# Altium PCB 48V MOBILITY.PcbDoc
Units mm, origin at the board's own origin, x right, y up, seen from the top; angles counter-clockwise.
Board outline 151.6 x 51.1 mm, 2 copper layers (Top Layer, Bottom Layer), stack 1.671 mm thick; 69 components, 31 nets, 153 pads, 0 vias.
Unrouted connection lines stored in the file: 122.
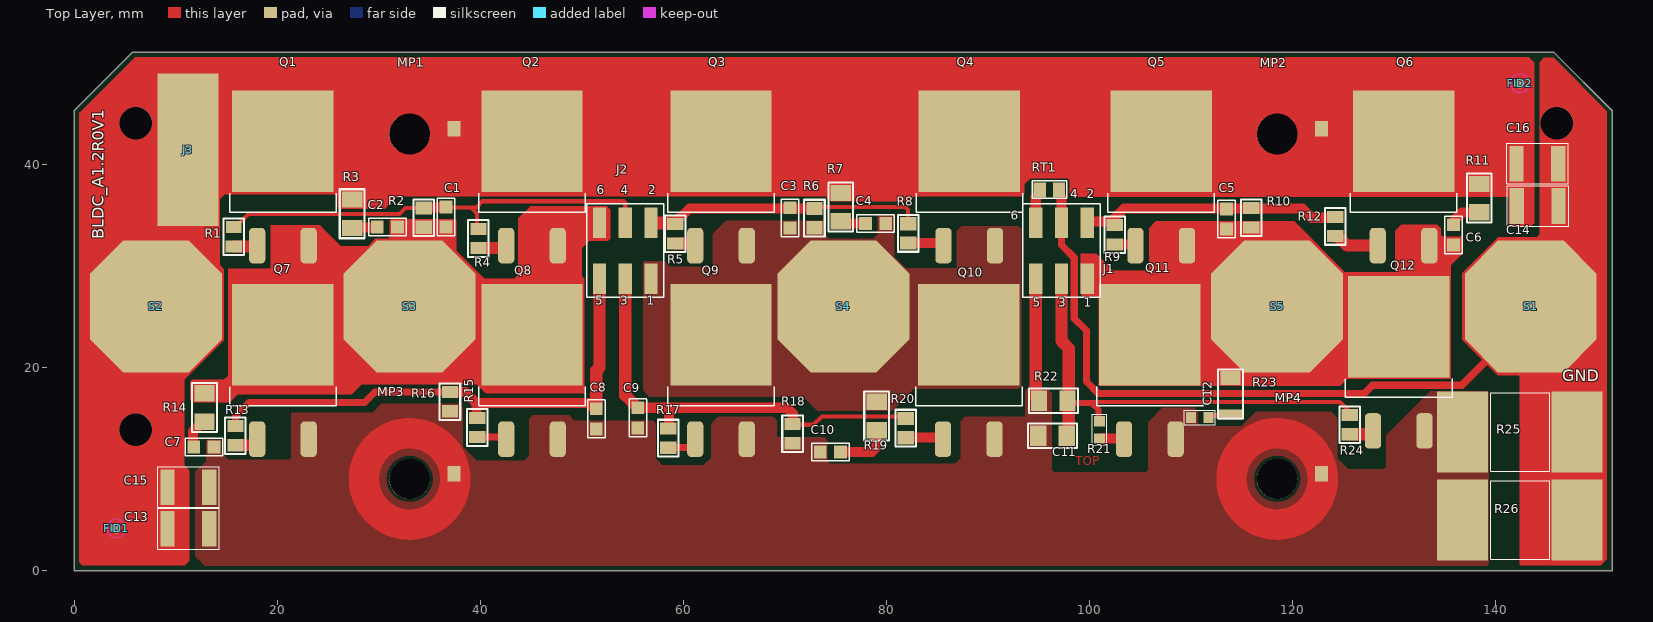
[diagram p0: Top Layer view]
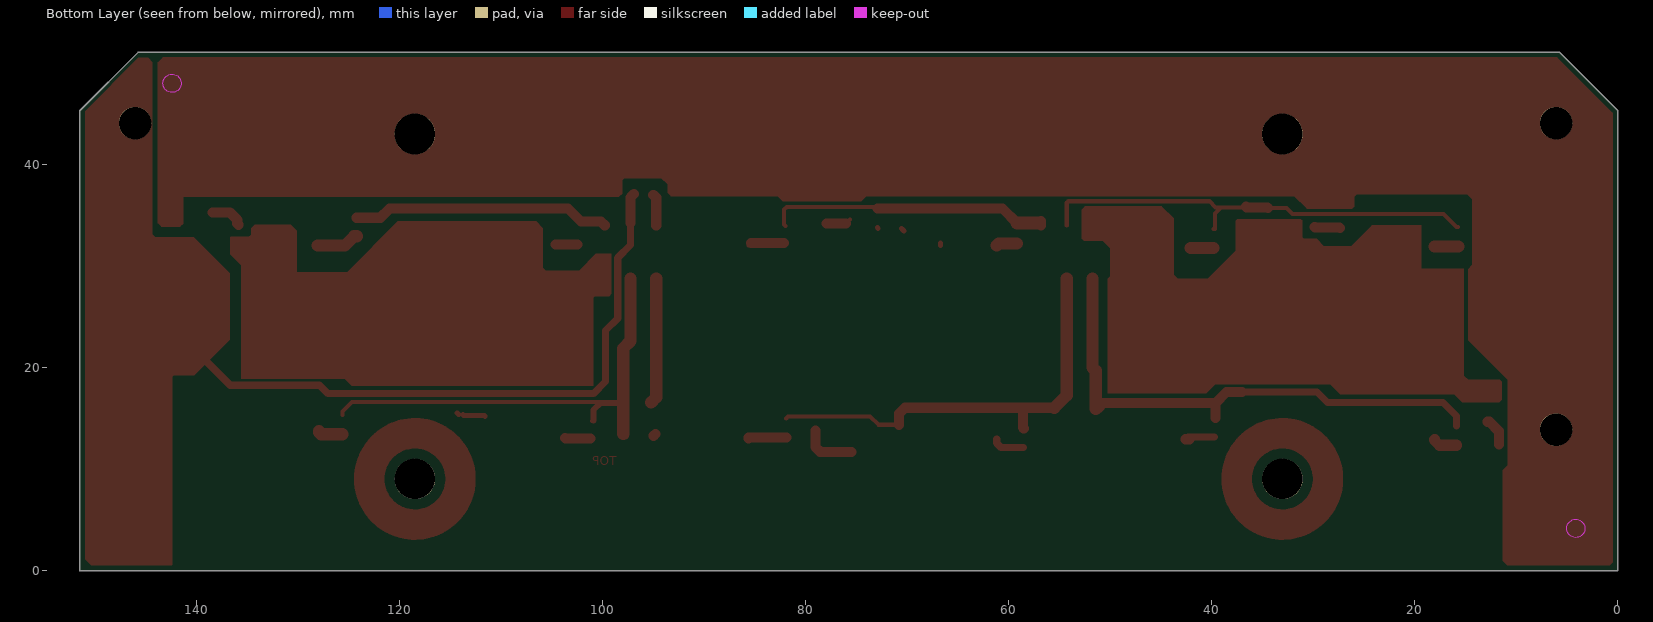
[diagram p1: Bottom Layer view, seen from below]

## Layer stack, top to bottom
Top Solder: solder mask 0.0102, Solder Resist, Dk 3.5
Top Layer: signal copper 0.0356
Dielectric 1: dielectric 1.6, FR-4, Dk 4.8
Bottom Layer: signal copper 0.0356
Bottom Solder: solder mask 0.0102, Solder Resist, Dk 3.5

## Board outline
-0.05,0 -0.05,45.3 cw(c0,45.3) -0.035,45.336 -0.036,45.336 5.664,51.036 5.664,51.035 cw(c5.7,51) 5.7,51.05 145.75,51.05 cw(c145.75,51) 145.786,51.035 145.786,51.036 151.536,45.286 151.535,45.286 cw(c151.5,45.25) 151.55,45.25 151.55,0 cw(c151.5,0) 151.5,-0.05 0,-0.05 cw(c0,0)

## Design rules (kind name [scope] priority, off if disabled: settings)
Clearance Clearance_3 [InNamedPolygon('TOP_LAYER_S2_P030')] p1: gap=0.254 ignorepadtopadclearanceinfootprint=FALSE
Clearance Clearance_2 [InNamedPolygon('TOP_LAYER_S4_P036')] p2: gap=0.254 ignorepadtopadclearanceinfootprint=FALSE
Clearance "GND POLYGON" [InNamedPolygon('TOP_LAYER_GNDINT_P037')] p3: gap=0.254 ignorepadtopadclearanceinfootprint=FALSE
Clearance Clearance_1 [InNamedPolygon('TOP_LAYER_S2_P030')] p4: gap=0.254 ignorepadtopadclearanceinfootprint=FALSE
Clearance [All] p5: gap=0.254 ignorepadtopadclearanceinfootprint=FALSE
PlaneConnect [All] p1: planeconnectstyle=Direct reliefexpansion=0.508 reliefentries=4 reliefconductorwidth=0.254 reliefairgap=0.254
PolygonConnect [All] p1: connectstyle=Direct reliefconductorwidth=0.254 reliefentries=4 polygonreliefangle="90 Angle" airgapwidth=0.254
RoutingVias [All] p1: holewidth=0.711 width=1.27 viastyle="Through Hole" minholewidth=0.711 minwidth=1.27 maxholewidth=0.711 maxwidth=1.27
SolderMaskExpansion [All] p1: expansion=0.102
Width [All] p1: maxlimit=100 minlimit=0.254 preferedwidth=0.4 minimp=50.000000 maximp=50.000000 favimp=50.000000
29 further rules are at their usual default settings.

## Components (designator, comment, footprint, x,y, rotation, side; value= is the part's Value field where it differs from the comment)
C1 "1nF/100V" CAP_0805 36.575,34.822 r90 top
C2 "10nF/100V" CAP_0805 30.81,33.833 r0 top
C3 "1nF/100V" CAP_0805 70.498,34.725 r90 top
C4 "10nF/100V" CAP_0805 78.925,34.194 r180 top
C5 "1nF/100V" CAP_0805 113.525,34.625 r90 top
C6 "10nF/100V" CAP_0805 135.875,33.05 r90 top
C7 "10nF/100V" CAP_0805 12.725,12.145 r180 top
C8 "1nF/100V" CAP_0805 51.398,14.92 r90 top
C9 "1nF/100V" CAP_0805 55.485,15.022 r90 top
C10 "10nF/100V" CAP_0805 74.473,11.67 r0 top
C11 "1nF/100V" MY_1206#1 96.342,13.284 r0 top
C12 "10nF/100V" MY_0603 110.871,15.06 r0 top
C13 "10uF/100V" CAP_1812 11.2,4.094 r180 top
C14 "10uF/100V" CAP_1812 144.182,35.9 r180 top
C15 "10uF/100V" CAP_1812 11.2,8.2 r180 top
C16 "10uF/100V" CAP_1812 144.157,40.075 r180 top
FID1 "FID_1MM" FID_40X20D 4.071,4.127 r0 top
FID2 "FID_1MM" FID_40X20D 142.429,47.992 r90 top
J1 "1241050-3" 1241050-3 97.25,31.5 r180 top locked
J2 "1241050-3" 1241050-3 54.25,31.5 r180 top locked
J3 "78X157 PAD" "VDDS PAD" 10.772,-12.218 r90 top
MP1 "M5x4mm" "POWER PAD" 33,43 r0 top locked
MP2 "M5x4mm" "POWER PAD" 118.5,43 r0 top locked
MP3 "M5x4mm" "POWER PAD" 33,9 r0 top locked
MP4 "M5x4mm" "POWER PAD" 118.5,9 r0 top locked
Q1 "HYG085N04LA1D" D2PAK -12.886,157.146 r0 top
Q2 "HYG085N04LA1D" D2PAK 11.659,157.146 r0 top
Q3 "HYG085N04LA1D" D2PAK 30.289,157.146 r0 top
Q4 "HYG085N04LA1D" D2PAK 54.759,157.146 r0 top
Q5 "HYG085N04LA1D" D2PAK 73.674,157.146 r0 top
Q6 "HYG085N04LA1D" D2PAK 97.559,157.146 r0 top
Q7 "HYG085N04LA1D" D2PAK -12.886,138.071 r0 top
Q8 "HYG085N04LA1D" D2PAK 11.659,138.071 r0 top
Q9 "HYG085N04LA1D" D2PAK 30.289,138.071 r0 top
Q10 "HYG085N04LA1D" D2PAK 54.709,138.071 r0 top
Q11 "HYG085N04LA1D" D2PAK 72.559,138.071 r0 top
Q12 "HYG085N04LA1D" D2PAK 97.088,138.884 r0 top
R1 "39R" MY_0805#1 15.672,32.868 r90 top
R2 "10K" MY_0805#2 34.4,34.75 r90 top
R3 "10R" MY_1206#1 27.305,35.113 r90 top
R4 "39R" MY_0805#3 39.775,32.697 r90 top
R5 "39R" MY_0805#3 59.182,33.168 r90 top
R6 "10K" MY_0805#2 72.9,34.714 r90 top
R7 "10K" MY_1206#1 75.463,35.763 r90 top
R8 "39R" MY_0805#2 82.15,33.194 r90 top
R9 "39R" MY_0805#3 102.489,33.071 r90 top
R10 "10K" MY_0805#3 115.951,34.747 r90 top
R11 "10K" MY_1206#1 138.4,36.65 r90 top
R12 "39R" MY_0805#3 124.231,33.884 r90 top
R13 "39R" MY_0805#3 15.824,13.269 r90 top
R14 "10K" MY_1206#1 12.764,16.019 r90 top
R15 "39R" MY_0805#3 39.675,14.072 r90 top
R16 "10K" MY_0805#3 36.975,16.625 r90 top
R17 "39R" MY_0805#3 58.496,13.03 r90 top
R18 "10K" MY_0805#3 70.739,13.462 r90 top
R19 "100R" MY_1206#1 79,15.175 r90 top
R20 "39R" MY_0805#2 81.9,14.019 r90 top
R21 "39R" MY_0603 101,13.844 r90 top
R22 "10K" MY_1206#1 96.418,16.739 r0 top
R23 "100R" MY_1206#2 113.875,17.35 r90 top
R24 "39R" MY_0805#3 125.654,14.351 r90 top
R25 "0.5mΩ ±1% 5931" "CURRENT SENSE RESISTORS_5931" 142.418,4.953 r180 top
R26 "0.5mΩ ±1% 5931" "CURRENT SENSE RESISTORS_5931" 142.418,13.614 r180 top
RT1 "10K" RES_0805 96.063,37.49 r0 top
S1 "M4x20mm" "15MM SPACER"#1 72.034,23.714 r0 top
S2 "M4x20mm" "15MM SPACER"#2 -65.771,23.258 r0 top
S3 "M4x20mm" "15MM SPACER"#3 -40.446,23.714 r0 top
S4 "M4x20mm" "15MM SPACER"#4 3.354,23.714 r0 top
S5 "M4x20mm" "15MM SPACER"#5 47.104,23.714 r0 top

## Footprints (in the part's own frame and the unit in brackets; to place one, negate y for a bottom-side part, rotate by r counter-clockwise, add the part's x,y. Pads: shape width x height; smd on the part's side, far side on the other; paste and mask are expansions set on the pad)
"15MM SPACER"#1 [mm]
  oct 13x13 smd: 1(71.466,2.286)
  body extent 68.77,-1.71 76.77,6.28, height 15.2
"15MM SPACER"#2 [mm]
  oct 13x13 smd: 1(73.771,2.742)
  body extent 68.77,-1.71 76.77,6.28, height 15.2
"15MM SPACER"#3 [mm]
  oct 13x13 smd: 1(73.446,2.286)
  body extent 68.77,-1.71 76.77,6.28, height 15.2
"15MM SPACER"#4 [mm]
  oct 13x13 smd: 1(72.396,2.286)
  body extent 68.77,-1.71 76.77,6.28, height 15.2
"15MM SPACER"#5 [mm]
  oct 13x13 smd: 1(71.396,2.286)
  body extent 68.77,-1.71 76.77,6.28, height 15.2
1241050-3 [mm] "1241050-3"
  rect 1.3x3 smd: 1(-2.54,-2.754) 2(-2.54,2.754) 3(0,-2.754) 4(0,2.754) 5(2.54,-2.754) 6(2.54,2.754)
  silkscreen extent -3.81,-4.6 3.81,4.6, body extent -3.81,-3.75 3.81,3.75, height 9.57
CAP_0805 [mm] "Ceramic Capacitor"
  rect 1.27x1.27 smd mask+0.076: 1(-1,0) 2(1,0)
  silkscreen extent -1.86,-0.86 1.86,0.86, body extent -1,-0.62 1,0.63, height 0.78
CAP_1812 [mm] "CAP_1812"
  rect 1.4x3.51 smd: 1(-2.057,0) 2(2.057,0)
  silkscreen extent -3.05,-2 3.01,2, body extent -2.25,-1.6 2.25,1.6, height 1.1
"CURRENT SENSE RESISTORS_5931" [mm]
  rect 5x8 smd: 1(-5.65,0) 2(5.65,0)
  silkscreen extent -2.95,-3.89 2.84,3.86, body extent -7.5,-3.87 7.5,3.88, height 1.13
D2PAK [mm]
  rrect50% 1.6x3.5 smd: 1(30.861,-125.152) 2(35.941,-125.152)
  rect 10x10 smd paste-7: 3(33.401,-114.877)
  silkscreen extent 28.15,-121.85 38.65,-120, body extent 28.4,-124.97 38.4,-110.02, height 4.51
FID_40X20D [mm]
  round 1 smd mask+0: ""(0,0)
  Keep-Out Layer circle w0.05: c0,0 r0.9
MY_0603 [mm]
  rect 1x1.1 smd: 1(-0.85,0) 2(0.85,0)
  silkscreen extent -1.52,-0.71 1.52,0.71, body extent -0.8,-0.4 0.8,0.4, height 0.44
MY_0805#1 [mm] "Resister"
  rect 1.2x1.6 smd: 1(-0.95,0)
  rect 1.2x1.5 smd: 2(0.95,0)
  silkscreen extent -1.8,-1.02 1.8,1.02, body extent -1,-0.62 1,0.63, height 0.59
MY_0805#2 [mm]
  rect 1.3x1.6 smd: 1(-0.95,0) 2(0.95,0)
  silkscreen extent -1.8,-1.02 1.8,1.02, body extent -1,-0.62 1,0.63, height 0.59
MY_0805#3 [mm]
  rect 1.2x1.6 smd: 1(-0.95,0) 2(0.95,0)
  silkscreen extent -1.8,-1.02 1.8,1.02, body extent -1,-0.62 1,0.63, height 0.59
MY_1206#1 [mm]
  rect 1.6x2 smd: 1(-1.375,-0.025) 2(1.425,-0.025)
  silkscreen extent -2.39,-1.24 2.44,1.19, body extent -1.57,-0.83 1.63,0.77, height 0.59
MY_1206#2 [mm]
  rect 1x2.5 smd: 1(-2,-0.025)
  rect 1.4x2 smd: 2(1.6,-0.025)
  silkscreen extent -2.39,-1.24 2.44,1.19, body extent -1.57,-0.83 1.63,0.77, height 0.59
"POWER PAD" [mm]
  rect 1.3x1.5 smd mask+0.076: 1(4.379,0.508)
  round 4 hole 4 unplated: ""(0,0)
  Top Layer circle w3: c0,0 r4.5
RES_0805 [mm] "Resister"
  rect 1.2x1.5 smd mask+0.076: 1(0.95,0) 2(-0.95,0)
  silkscreen extent -1.7,-0.84 1.7,0.89, body extent -1,-0.63 1,0.62, height 0.5
"VDDS PAD" [mm]
  rect 15x6 smd: 1(53.661,-0.378)

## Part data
C1 C2 C3 C4 C5 C6 C7 C8 C9 C10 C11 C12: library part CAP_33pF-50V-5%-0805, "33pF ±5% 50V Ceramic Capacitor C0G, NP0 0805 (2012 Metric)", Alternate Part Number-1=NA, Case/Package=0805, Manufacturer=Samsung, Manufacturer Part Number=CL21C330JBANNNC, Supplier Part Number-1=0805N330J500CT
C13 C14 C15 C16: library part CAP_2.2uF-25V-10%-0805, "2.2µF ±10% 25V Ceramic Capacitor X7R 0805 (2012 Metric)", Alternate Part Number-1=NA, Case/Package=0805, Manufacturer=KEMET, Manufacturer Part Number=CL21B225KAFNFNE, Supplier Part Number-1=CL21A225KAFNNNE
FID1 FID2: "Fiducial 40 mil Diameter and 120 mil Mask"
J1 J2: "Connector", Manufacturer_Name="TE Connectivity", Mouser Part Number=571-1241050-3
J3: library part SMD_PAD-78X157, "SMD Pad of 2mm x 4mm 1 pin", Alternate Part Number-1=NA, Case/Package=SMD
MP1 MP2 MP3 MP4: library part 7466105R, "WP-SMBU SMT Internal blind-hole thread with pins, OD 9mm, M5x4mm, 70A", Manufacturer="Wurth Elektronik", Operating Temperature="-55 to +150degC", Rated Current=70A
Q1 Q2 Q3 Q4 Q5 Q6 Q7 Q8 Q9 Q10 Q11 Q12: library part IRFRC20, "HEXFET Power MOSFET"
R1 R4 R5 R8 R9 R12 R13 R15 R16 R17 R18 R20 R21 R22: library part RES_39R-3W-5%-TH, "39 Ohms ±5% 3W Through Hole Resistor Axial Flame Proof, Safety Wirewound", Alternate Part Number-1=NA, Case/Package=TH, Manufacturer="Stackpole Electronics", Manufacturer Part Number=RWM041039R0JR15E1, Supplier Part Number-1=72-RWM410-39-5
R2 R6 R10: library part RES_10K-0.1W-1%-0603, "10 kOhms ±1% 0.1W, 1/10W Chip Resistor 0603 (1608 Metric) Automotive AEC-Q200 Thick Film", Alternate Part Number-1=0603WAJ0103T5E, Case/Package=0603, Manufacturer=Walsin, Manufacturer Part Number=WR06X1002FTL
R3 R7 R11 R14 R19 R23: library part RES_100R-0.1W-1%-0603, "100 Ohms ±1% 0.1W, 1/10W Chip Resistor 0603 (1608 Metric) Thick Film", Alternate Part Number-1=MR06X1000FTL, Case/Package=0603, Manufacturer=Walsin, Manufacturer Part Number=WR06X1000FTL, Supplier Part Number-1=WALSIN:WR06X1000FTL
R24: library part RES_39R-3W-5%-TH, "390 Ohms ±5% 3W Through Hole Resistor Axial Flame Proof, Safety Wirewound", Alternate Part Number-1=NA, Case/Package=TH, Manufacturer="Stackpole Electronics", Manufacturer Part Number=RWM041039R0JR15E1, Supplier Part Number-1=72-RWM410-39-5
R25 R26: library part CR0603-JW-150ELF, "Resistor", Manufacturer_Name=Bourns
RT1: library part RT_10K-0805, "NTC Thermistor 10k 0805 (2012 Metric)", Alternate Part Number-1=NA, Case/Package=0805, Manufacturer="Vishay BCcomponents", Manufacturer Part Number=NCP21XV103J03RA
S1 S2 S3 S4 S5: library part 9774010482, "WA-SMSI SMT Steel Spacer, internal Thread, OD 8.2mm, M4x1mm", Manufacturer="Wurth Elektronik", Operating Temperature="-55 to +150degC"

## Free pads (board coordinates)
  round 3.2 hole 3.2 unplated: ""(6.023,13.867) ""(6.023,44.073) ""(146.075,44.073)

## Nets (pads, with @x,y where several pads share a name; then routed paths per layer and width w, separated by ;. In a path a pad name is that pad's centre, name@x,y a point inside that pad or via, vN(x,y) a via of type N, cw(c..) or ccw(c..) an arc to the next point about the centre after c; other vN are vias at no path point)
GNDINT: C14.1 C16.1 J1.3 R25.1 R26.1 RT1.1 S1.1 | length 68.1
  Top Layer w0.7: J1.3 97.25,32.05 98.504,30.796 98.504,24.813 99.7,23.617 99.7,18.599 100.895,17.404 127.056,17.404 127.889,18.237 136.703,18.237 143.5,25.034 S1.1
  Top Layer w1: RT1.1@96.9,37.1 97.25,36.75 J1.3
NetC1_2: C1.2 J2.3 R1.2 R2.2 R4.2 | length 44.5
  Top Layer w0.4: R1.2 15.822,33.818 17.106,35.101 32.008,35.101 32.606,35.7 R2.2 ; C1.2 36.622,35.775 39.033,35.775 ; R4.2 39.625,33.647 39.625,35.183 39.033,35.775 ; J2.3@54.25,34 54.25,36.225 54.102,36.373 40.173,36.373 39.575,35.775 39.033,35.775
  Top Layer w1: R2.2 34.461,35.761 36.514,35.761 C1.2
NetC2_1: C2.1 R3.1 | length 2.5
  Top Layer w1: R3.1 27.378,33.786 29.763,33.786 C2.1
NetC3_2: C3.2 J2.1 R5.2 R6.2 R8.2 | length 28.3
  Top Layer w0.4: R6.2 73.059,35.823 81.846,35.823 82.1,35.569 82.1,34.069 R8.2@81.95,33.919
  Top Layer w1: J2.1@56.79,34 56.79,34.429 J2.1@57.005,34.214 ; R5.2@59.135,34.214 60.586,35.664 R6.2
  Top Layer w1.3: J2.1@57.005,34.214 R5.2@59.135,34.214
NetC4_2: C4.2 R7.1 | length 2.5
  Top Layer w0.4: R7.1@75.625,34.569 R7.1@76.001,34.194
  Top Layer w1: R7.1@76.001,34.194 C4.2
NetC5_2: C5.2 J1.1 R9.2 R10.2 R12.2 | length 25.6
  Top Layer w0.6: C5.2@113.525,35.45 C5.2@113.591,35.516
  Top Layer w1: J1.1@99.79,34 100.165,34.375 102.125,34.375 103.414,35.664 120.986,35.664 121.903,34.747 R12.2@124.254,34.747
NetC6_2: C6.2 R11.1 | length 3.3
  Top Layer w1: C6.2 136.01,34.185 136.01,34.537 136.748,35.275 R11.1
NetC7_2: C7.2 R14.1 | length 2.8
  Top Layer w1: C7.2@11.659,12.386 11.659,13.714 12.589,14.644 R14.1
NetC8_2: C8.2 J2.6 R13.2 R15.2 R16.2 | length 52.3
  Top Layer w0.7: R13.2 15.824,15.189 17.17,16.535 28.55,16.535 29.576,17.562 R16.2@36.988,17.562
  Top Layer w1: R16.2@36.988,17.562 38.506,17.562 39.575,16.494 ; R15.2@39.575,15.019 39.575,16.494 ; C8.2@51.096,16.022 50.625,16.494 39.575,16.494
  Top Layer w1.2: C8.2@51.433,15.955 C8.2 51.398,19.673 51.71,19.985 J2.6
NetC9_2: C9.2 J2.4 R17.2 R18.2 R20.2 | length 48
  Top Layer w0.4: R18.2 70.739,14.38 70.775,14.344 72.814,14.344 73.635,15.165 81.704,15.165 R20.2@81.9,14.969
  Top Layer w0.6: 64.098,16.194 68.575,16.194
  Top Layer w1: C9.2 58.572,16.022 ; R17.2 58.572,14.056 58.572,16.022 ; R18.2@70.775,14.344 70.775,15.447 70.2,16.022 58.572,16.022
  Top Layer w1.2: J2.4 54.25,17.257 C9.2
NetC10_2: C10.2 R19.1 | length 5.3
  Top Layer w1: C10.2 78.552,11.671 79.025,12.144 R19.1@79.025,13.744
NetC11_2: C11.2 J1.4 R21.2 R22.2 R24.2 | length 46.9
  Top Layer w0.4: C11.2@97.53,13.496 C11.2 ; R22.2@97.99,16.613 R22.2@98.103,16.5 ; 100.203,16.5 100.303,16.6 124.709,16.6 125.654,15.656 R24.2 ; R21.2@100.909,14.784 R21.2 R21.2@101.05,14.694
  Top Layer w0.6: R22.2@98.103,16.5 100.203,16.5 100.909,15.794 R21.2@100.909,14.784
  Top Layer w0.7: C11.2 C11.2@97.966,13.457
  Top Layer w1.2: J1.4 97.25,22.587 97.966,21.871 97.966,16.613 C11.2@97.966,13.457
NetC12_2: C12.2 R23.1 | length 2.5
  Top Layer w0.5: C12.2@111.575,15.179 111.661,15.264 113.689,15.264 R23.1@113.775,15.35 ; R23.1@114.176,15.35 R23.1@114.325,15.5
NetJ1_5: J1.5 RT1.2 | length 3.1
  Top Layer w1: J1.5@94.71,34 J1.5 94.71,36.71 RT1.2@95,37
NetQ1_1: Q1.1 R1.1 | length 2.4
  Top Layer w0.6: Q1.1 18.025,31.944 Q1.1@17.999,31.918
  Top Layer w1.2: R1.1 Q1.1@17.999,31.918
NetQ2_1: Q2.1 R4.1 | length 2.6
  Top Layer w0.4: Q2.1@42.024,31.747 Q2.1@42.27,31.994
  Top Layer w1.2: R4.1 Q2.1@42.024,31.747
NetQ3_1: Q3.1 R5.1 | length 2.1
  Top Layer w1.2: R5.1 60.95,32.218 61.15,32.018 Q3.1
NetQ4_1: Q4.1 R8.1 | length 3.6
  Top Layer w0.4: Q4.1@85.37,32.244 Q4.1
  Top Layer w1: R8.1 Q4.1@85.37,32.244
NetQ5_1: Q5.1 R9.1 | length 3
  Top Layer w0.4: Q5.1@104.21,31.994 Q5.1@104.235,32.019
  Top Layer w0.6: Q5.1@104.235,32.019 Q5.1@104.735,32.019
  Top Layer w0.7: Q5.1 104.71,31.994 104.735,32.019 Q5.1@104.633,32.121
  Top Layer w1: R9.1 Q5.1@104.633,32.121
NetQ6_1: Q6.1 R12.1 | length 4.2
  Top Layer w1.2: R12.1@124.231,32.918 124.485,32.918 125.41,31.994 Q6.1@128.075,31.994
NetQ7_1: Q7.1 R13.1 | length 2.6
  Top Layer w1: Q7.1@17.525,12.319 17.975,12.769 Q7.1 Q7.1@18.024,12.87
  Top Layer w1.1: R13.1 Q7.1@17.525,12.319
NetQ8_1: Q8.1 R15.1 | length 3.3
  Top Layer w0.7: R15.1 42.317,13.122 Q8.1
  Top Layer w1: Q8.1@42.145,12.919 Q8.1
NetQ9_1: Q9.1 R17.1 | length 3.2
  Top Layer w0.7: R17.1 60.704,12.08 61.15,12.526 Q9.1
NetQ10_1: Q10.1 R20.1 | length 3.8
  Top Layer w1: R20.1@81.9,13.069 85.566,13.069 85.62,13.015 Q10.1@85.62,13.057
NetQ11_1: Q11.1 R21.1 | length 2.6
  Top Layer w1: R21.1@101.175,12.994 103.66,12.994 Q11.1@103.71,13.044
NetQ12_1: Q12.1 R24.1 | length 2.5
  Top Layer w1.2: R24.1 127.749,13.401 127.949,13.601 Q12.1
S2: C1.1 C2.2 J2.5 Q1.2 Q2.2 Q7.3 Q8.3 R2.1 R14.2 S3.1
S3: C3.1 C4.1 J2.2 Q3.2 Q4.2 Q9.3 Q10.3 R6.1 R19.2 S4.1 | length 0.7
  Top Layer w0.5: Q3.2@66.705,31.994 Q3.2@66.705,32.255 ; C3.1@70.286,33.432 70.498,33.644 C3.1@70.558,33.704 ; R6.1@72.84,33.704 R6.1
S4: C5.1 C6.1 J1.2 Q5.2 Q6.2 Q11.3 Q12.3 R10.1 R23.2 S5.1
SHUNT+: C7.1 C8.1 C9.1 C10.1 C11.1 C12.1 C13.1 C15.1 J1.6 MP3.1 MP4.1 Q7.2 Q8.2 Q9.2 Q10.2 Q11.2 Q12.2 R16.1 R18.1 R22.1 R25.2 R26.2 | length 12.7
  Top Layer w1: C11.1@94.788,13.439 C11.1
  Top Layer w1.2: J1.6@94.718,28.738 J1.6 94.71,17.047 R22.1 R22.1@95.224,16.533
VDSS: C13.2 C14.2 C15.2 C16.2 J3.1 MP1.1 MP2.1 Q1.3 Q2.3 Q3.3 Q4.3 Q5.3 Q6.3 R3.2 R7.2 R11.2 S2.1
pads on no net: FID1. FID2. MP1. MP2. MP3. MP4.

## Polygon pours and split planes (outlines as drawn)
no net on Top Solder "Top Solder-No Net" (solid): 14.975,10.019
SHUNT+ on Top Layer "TOP_LAYER_SHUNT+_P053" (solid, pour order 53): 11.89,1.364 cw(c11.925,1.4) 11.875,1.4 11.875,9.65 cw(c11.925,9.65) 11.89,9.686 12.964,10.76 12.964,12.827 cw(c13.014,12.827) 13.014,12.877 14.402,12.877 cw(c14.402,12.827) 14.452,12.827 14.452,11.578 15.13,10.9 21.17,10.9 21.35,11.08 21.35,15.482 cw(c21.4,15.482) 21.4,15.532 29.345,15.532 30.206,16.393 cw(c30.242,16.358) 30.242,16.408 37.842,16.408 cw(c37.842,16.358) 37.878,16.393 38.211,16.061 cw(c38.176,16.025) 38.225,16.025 38.225,12.164 39.608,10.781 44.285,10.781 44.775,11.271 44.775,14.9 cw(c44.825,14.9) 44.79,14.936 45.129,15.276 cw(c45.165,15.24) 45.165,15.29 48.675,15.29 cw(c48.676,15.24) 48.711,15.275 49.236,14.75 56.953,14.75 cw(c56.953,14.7) 56.989,14.735 57.236,14.488 cw(c57.201,14.453) 57.251,14.453 57.251,10.999 57.906,10.344 61.962,10.344 62.713,11.095 62.713,14.427 cw(c62.763,14.427) 62.728,14.463 63.394,15.129 cw(c63.43,15.094) 63.43,15.144 68.825,15.144 cw(c68.825,15.094) 68.861,15.129 69.161,14.829 cw(c69.126,14.794) 69.175,14.794 69.175,13.265 69.321,13.119 73.831,13.119 cw(c73.831,13.069) 73.867,13.104 74.161,12.811 cw(c74.126,12.775) 74.175,12.775 74.175,10.755 74.412,10.519 86.773,10.519 87.3,11.046 87.3,14.675 cw(c87.35,14.675) 87.315,14.711 87.733,15.129 cw(c87.768,15.094) 87.769,15.144 93.682,15.144 93.682,17.707 cw(c93.732,17.707) 93.697,17.743 93.964,18.011 cw(c94,17.975) 94,18.025 95.687,18.025 cw(c95.687,17.975) 95.723,18.01 96.261,17.473 cw(c96.226,17.438) 96.275,17.437 96.275,9.921 96.527,9.669 105.573,9.669 105.817,9.913 105.817,14.617 cw(c105.867,14.617) 105.832,14.653 107.183,16.004 cw(c107.218,15.969) 107.219,16.019 110.295,16.019 cw(c110.295,15.969) 110.331,16.004 110.653,15.682 cw(c110.618,15.647) 110.667,15.646 110.667,14.397 110.871,14.194 114.961,14.194 116.398,15.631 cw(c116.433,15.596) 116.434,15.646 123.779,15.646 cw(c123.779,15.596) 123.815,15.631 124.436,15.011 cw(c124.401,14.975) 124.45,14.975 124.45,11.021 125.502,9.969 129.024,9.969 129.261,10.206 129.261,13.259 cw(c129.311,13.259) 129.276,13.295 133.645,17.663 cw(c133.68,17.628) 133.73,17.628 139.269,17.628 cw(c139.319,17.628) 139.369,17.628 139.369,0.678 cw(c139.319,0.678) 139.354,0.642 139.177,0.464 cw(c139.141,0.499) 139.141,0.45 12.825,0.45 cw(c12.825,0.5) 12.789,0.465
S3 on Top Layer "TOP_LAYER_S3_P041" (solid, pour order 41): 56.002,17.76 56.002,30.373 56.083,30.455 58.12,30.455 58.654,29.921 62.89,29.921 62.89,33.172 64.168,34.45 73.925,34.45 73.925,33.109 74.37,32.664 78.664,32.664 79.125,33.125 79.125,34.968 79.214,35.057 80.493,35.057 80.775,34.775 80.775,30.909 81.915,29.769 86.925,29.769 86.925,33.445 87.398,33.919 92.981,33.919 93.275,33.625 93.275,18.175 92.977,17.877 82.695,17.877 82.347,17.529 80.543,15.725 73.175,15.725 71.775,17.125 56.637,17.125
no net on Top Layer "TOP_LAYER_NONET_P033" (solid, pour order 33): 137.5,13.075

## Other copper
Top Layer:
  region net S2: 11.39,16.815 cw(c11.425,16.851) 11.375,16.851 11.375,18.525 cw(c11.425,18.525) 11.39,18.561 11.584,18.755 cw(c11.62,18.72) 11.62,18.77 14.686,18.77 15.1,19.184 15.1,29.655 cw(c15.15,29.655) 15.15,29.705 19.304,29.705 19.304,33.944 cw(c19.355,33.944) 19.355,33.994 24.156,33.994 cw(c24.156,33.944) 24.192,33.979 26.218,31.953 28.91,31.953 29.624,32.667 29.623,32.666 cw(c29.659,32.631) 29.659,32.681 30.891,32.681 31.05,32.84 31.05,34.45 cw(c31.1,34.45) 31.065,34.486 31.064,34.486 31.164,34.586 31.164,34.585 cw(c31.2,34.55) 31.2,34.6 37.422,34.6 cw(c37.422,34.55) 37.458,34.585 37.457,34.586 37.586,34.457 37.585,34.458 cw(c37.55,34.422) 37.6,34.422 37.6,31.483 40.333,28.75 43.329,28.75 43.714,29.135 43.714,34.639 cw(c43.764,34.639) 43.729,34.675 44.903,35.85 44.903,35.849 cw(c44.939,35.814) 44.939,35.864 52.426,35.864 cw(c52.426,35.814) 52.462,35.849 52.461,35.85 52.761,35.55 52.76,35.551 cw(c52.725,35.515) 52.775,35.515 52.775,32.71 cw(c52.725,32.71) 52.76,32.674 52.761,32.674 52.588,32.502 52.589,32.502 cw(c52.553,32.537) 52.553,32.487 50.722,32.487 49.95,31.715 49.95,28.971 50.201,28.721 50.2,28.721 cw(c50.165,28.685) 50.215,28.685 50.215,17.493 cw(c50.165,17.493) 50.165,17.443 40.52,17.443 cw(c40.52,17.493) 40.484,17.458 40.485,17.458 39.629,18.314 28.266,18.314 27.315,17.363 27.316,17.364 cw(c27.28,17.399) 27.28,17.349 16.048,17.349 15.276,16.576 cw(c15.24,16.612) 15.24,16.561 11.665,16.561 cw(c11.665,16.612) 11.629,16.576
  region net VDSS: 0.739,0.49 ccw(c0.775,0.525) 0.775,0.475 10.775,0.475 ccw(c10.775,0.525) 10.811,0.49 10.811,0.489 11.261,0.939 11.26,0.939 ccw(c11.225,0.975) 11.275,0.975 11.275,9.844 ccw(c11.225,9.844) 11.26,9.88 11.261,9.879 10.775,10.364 10.775,18.754 14.686,22.664 14.685,22.664 ccw(c14.65,22.7) 14.7,22.7 14.7,29.65 ccw(c14.65,29.65) 14.685,29.686 14.686,29.686 14.275,30.096 14.275,36.582 14.762,37.068 25.661,37.068 25.925,36.804 25.925,35.875 ccw(c25.975,35.875) 25.94,35.839 25.939,35.839 26.114,35.664 26.114,35.665 ccw(c26.15,35.7) 26.15,35.65 30.575,35.65 ccw(c30.575,35.7) 30.611,35.665 30.611,35.664 31.821,36.875 74.004,36.875 74.514,36.364 74.514,36.365 ccw(c74.55,36.4) 74.55,36.35 82.2,36.35 ccw(c82.2,36.4) 82.236,36.365 82.236,36.364 82.746,36.875 93.237,36.875 ccw(c93.237,36.925) 93.273,36.89 93.272,36.889 93.584,37.201 93.584,37.2 ccw(c93.548,37.236) 93.599,37.236 93.599,38.028 94.204,38.634 97.871,38.634 98.07,38.435 98.07,37.16 ccw(c98.12,37.16) 98.085,37.124 98.085,37.125 98.395,36.814 98.394,36.815 ccw(c98.43,36.85) 98.43,36.8 120.65,36.8 141.325,36.8 141.325,34.2 ccw(c141.375,34.2) 141.34,34.164 141.339,34.164 141.621,33.883 141.62,33.883 ccw(c141.656,33.919) 141.656,33.868 143.469,33.868 ccw(c143.469,33.919) 143.505,33.883 143.504,33.883 143.811,34.189 143.81,34.189 ccw(c143.775,34.225) 143.825,34.225 143.825,50.05 ccw(c143.775,50.05) 143.81,50.086 143.811,50.086 143.361,50.536 143.361,50.535 ccw(c143.325,50.5) 143.325,50.55 5.925,50.55 ccw(c5.925,50.5) 5.889,50.535 5.889,50.536 0.464,45.111 0.465,45.111 ccw(c0.5,45.075) 0.45,45.075 0.45,0.8 ccw(c0.5,0.8) 0.465,0.764 0.464,0.764
  region net GNDINT: 140.259,19.202 142.265,19.202 142.418,19.05 142.418,0.524 142.442,0.5 150.393,0.5 151,1.107 151,45.25 145.75,50.5 144.8,50.5 144.374,50.074 144.374,33.096 144.101,32.824 140.291,32.824 138.709,31.241 136.754,29.286 136.754,22.708
  region net S4: 99.365,27 100.768,27 100.932,26.836 100.932,18.194 124.747,18.194 125.434,18.881 135.636,18.881 135.636,30.074 136.7,31.138 136.7,32.8 136.65,32.85 134.85,32.85 134.625,33.075 134.625,33.725 134.425,33.925 134.275,34.075 130.714,34.075 130.119,33.48 130.119,29.388 125.171,29.388 120.167,34.392 106.553,34.392 105.893,33.731 105.893,29.82 105.613,29.54 102.31,29.54 100.675,31.175 99.136,31.175 99.136,27.229
  pour cut-out: 111.564,32.73
  text "TOP" at 98.603,10.058 h1.5

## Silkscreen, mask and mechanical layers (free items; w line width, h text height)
Top Overlay:
  text "6" at 51.425,36.764 h1.5
  text "4" at 53.8,36.765 h1.5
  text "2" at 56.5,36.764 h1.5
  text "4" at 98.103,36.373 h1.5
  text "2" at 99.72,36.355 h1.5
  text "6" at 92.25,34.275 h1.5
  text "BLDC_A1.2R0V1" at 3.226,32.614 h2 r90
  text "5" at 51.275,25.868 h1.5
  text "3" at 53.775,25.85 h1.5
  text "1" at 56.375,25.85 h1.5
  text "5" at 94.4,25.675 h1.5
  text "3" at 96.95,25.685 h1.5
  text "1" at 99.425,25.675 h1.5
  text "GND" at 146.609,18.237 h2
Top Solder:
  drawing of 2 lines, arcs and shapes, not listed
Mechanical 2:
  lines w0.1: 0.043,45.343 5.7,51 ; 145.775,50.975 151.475,45.275 ; 5.7,51 145.75,51 151.5,45.25 151.5,0 0,0 0,45.3 5.7,51 ; 0.5,0.5 0.5,45.075 5.925,50.5 145.75,50.5 151,45.25 151,0.5 0.5,0.5
Mechanical 8:
  drawing of 171 lines, arcs and shapes, not listed
Mechanical 11:
  lines w0.1: 69.657,13.069 73.831,13.069 74.125,12.775 74.125,12.624 74.125,10.734 74.391,10.469 86.794,10.469 87.35,11.025 87.35,14.675 87.769,15.094 91.85,15.094 93.732,15.094 93.732,17.707 94,17.975 95.687,17.975 96.225,17.437 96.225,9.9 96.506,9.619 105.594,9.619 105.867,9.892 105.867,13.661 105.867,14.617 107.219,15.969 110.295,15.969 110.617,15.646 110.617,14.376 110.85,14.144 112.725,14.144 114.982,14.144 116.434,15.596 123.779,15.596 124.4,14.975 124.4,11 125.481,9.919 127,9.919 ; 70.025,13.069 69.3,13.069 69.125,13.244 69.125,14.794 68.825,15.094 64.081,15.094 63.43,15.094 62.763,14.427 62.763,11.074 61.983,10.294 60.481,10.294 57.885,10.294 57.201,10.978 57.201,14.453 56.953,14.7 49.215,14.7 48.675,15.24 45.165,15.24 44.825,14.9 44.825,12.694 44.825,11.25 44.306,10.731 39.588,10.731 38.175,12.144 38.175,16.025 37.842,16.358 30.242,16.358 29.366,15.482 21.4,15.482 21.4,15.069 21.4,11.059 21.191,10.85 16.658,10.85 15.109,10.85 14.402,11.557 14.402,12.827 13.014,12.827 13.014,10.739 11.925,9.65 11.925,1.4 12.825,0.5 139.141,0.5 139.319,0.678 139.319,17.628 133.68,17.628 129.311,13.259 129.311,10.185 129.045,9.919 126.65,9.919 ; 136.906,22.733 136.906,29.231 138.789,31.114 140.275,32.6 144.15,32.6 145.288,33.738 145.288,50.19 145.806,50.19 150.647,45.349 150.647,0.754 150.417,0.524 146.853,0.524 145.679,0.524 145.491,0.711 145.491,19.329 140.31,19.329 136.906,22.733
